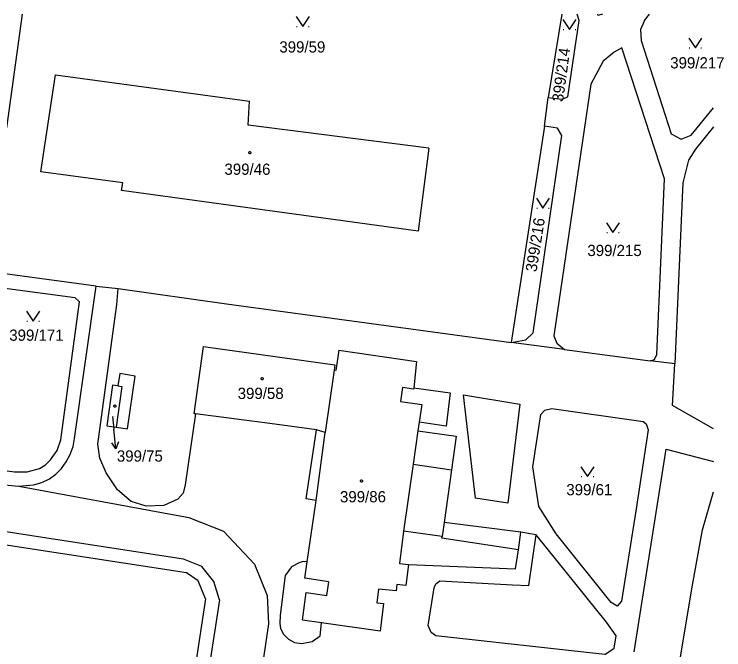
# Model space of a CAD drawing. Extents: x -851495 to -851222, y -1010479 to -1010202.
# Drawn here: x -851333.3 to -851225.9, y -1010299.4 to -1010203.3 of the extents above; entities that cross this region are included whole.
import ezdxf

# ---------------------------------------------------------------- set-up
doc = ezdxf.new("R2010")
doc.units = 0
for name, color, linetype in [('1', 7, 'Continuous'), ('12', 7, 'Continuous'), ('2', 7, 'Continuous'), ('3', 7, 'Continuous'), ('4', 7, 'Continuous'), ('5', 7, 'Continuous'), ('7', 7, 'Continuous')]:
    doc.layers.add(name, color=color, linetype=linetype)

# ---------------------------------------------------------------- blocks, each defined once
blk = doc.blocks.new('314')
for p, q in [((-0.95, 0), (-0.85, 0)), ((0.85, 0), (0.95, 0))]:
    blk.add_line(p, q)
blk.add_lwpolyline([(-1, 1.5), (0, 0), (1, 1.5)])
blk = doc.blocks.new('10292')
blk.add_line((0, 3), (0, 0))
blk.add_lwpolyline([(-0.5, 2), (0, 3), (0.5, 2)])
blk = doc.blocks.new('404')
blk.add_lwpolyline([(0, 0.17), (0.1, 0.15), (0.15, 0.06), (0.17, 0), (0.15, -0.09), (0.07, -0.16), (0, -0.17), (-0.09, -0.14), (-0.15, -0.08), (-0.17, 0), (-0.15, 0.09), (-0.07, 0.16), (0, 0.17)])

msp = doc.modelspace()

# ---------------------------------------------------------------- linework, layer by layer
at = {"layer": '1'}
for p, q in [((-851332.03, -1010203.26), (-851334.4, -1010220.43)), ((-851250.46, -1010203.26), (-851252.5, -1010215.86)), ((-851247.84, -1010204.19), (-851248.14, -1010203.26)), ((-851244.95, -1010203.46), (-851245.01, -1010203.26)), ((-851244.27, -1010203.26), (-851244.95, -1010203.46)), ((-851237.92, -1010204.22), (-851237.16, -1010203.26)), ((-851249.53, -1010215.73), (-851247.84, -1010204.19)), ((-851237.92, -1010204.22), (-851238.56, -1010205.58)), ((-851238.56, -1010205.58), (-851238.43, -1010207.26)), ((-851238.43, -1010207.26), (-851233.9, -1010221.36)), ((-851241.37, -1010208.36), (-851242.53, -1010208.98)), ((-851234.92, -1010228.17), (-851241.37, -1010208.36)), ((-851242.53, -1010208.98), (-851244.17, -1010210.38)), ((-851244.17, -1010210.38), (-851246.06, -1010213.84)), ((-851329.23, -1010227.1), (-851326.99, -1010212.43)), ((-851326.99, -1010212.43), (-851297.68, -1010216.41)), ((-851246.06, -1010213.84), (-851251.65, -1010251.91)), ((-851253.05, -1010220.18), (-851252.5, -1010215.86)), ((-851252.5, -1010215.86), (-851250.44, -1010216.12)), ((-851250.44, -1010216.12), (-851249.53, -1010215.73)), ((-851297.88, -1010220.05), (-851297.68, -1010216.41)), ((-851230.87, -1010221.56), (-851227.5, -1010217.44)), ((-851270.53, -1010223.5), (-851297.88, -1010220.05)), ((-851253.05, -1010220.18), (-851258.09, -1010252.91)), ((-851251.08, -1010220.48), (-851253.05, -1010220.18)), ((-851250.42, -1010221.62), (-851251.08, -1010220.48)), ((-851227.5, -1010220.29), (-851230.21, -1010223.65)), ((-851233.9, -1010221.36), (-851232.4, -1010222.15)), ((-851232.4, -1010222.15), (-851230.87, -1010221.56)), ((-851254.8, -1010251.46), (-851250.42, -1010221.62)), ((-851270.53, -1010223.5), (-851272.17, -1010236.09)), ((-851230.21, -1010223.65), (-851231.29, -1010225.34)), ((-851231.29, -1010225.34), (-851232.13, -1010228.78)), ((-851316.84, -1010228.77), (-851329.23, -1010227.1)), ((-851317.04, -1010229.92), (-851316.84, -1010228.77)), ((-851236.07, -1010254.72), (-851234.92, -1010228.17)), ((-851232.13, -1010228.78), (-851233.33, -1010256.15)), ((-851272.17, -1010236.09), (-851317.04, -1010229.92)), ((-851324.05, -1010246.13), (-851347.89, -1010243.01)), ((-851320.86, -1010244.4), (-851337.25, -1010242.19)), ((-851324.12, -1010267.41), (-851320.86, -1010244.4)), ((-851320.86, -1010244.4), (-851317.53, -1010244.75)), ((-851317.53, -1010244.75), (-851301.15, -1010247.03)), ((-851323.38, -1010246.75), (-851324.05, -1010246.13)), ((-851326.2, -1010267.63), (-851323.38, -1010246.75)), ((-851301.15, -1010247.03), (-851272.18, -1010251.01)), ((-851272.18, -1010251.01), (-851258.09, -1010252.91)), ((-851255.88, -1010252.52), (-851254.8, -1010251.46)), ((-851258.09, -1010252.91), (-851255.88, -1010252.52)), ((-851251.65, -1010251.91), (-851251.18, -1010253)), ((-851306.04, -1010263.67), (-851304.62, -1010253.53)), ((-851304.62, -1010253.53), (-851284.78, -1010256.27)), ((-851250.03, -1010253.97), (-851258.09, -1010252.91)), ((-851251.18, -1010253), (-851250.03, -1010253.97)), ((-851284.14, -1010254.06), (-851284.64, -1010257.12)), ((-851284.14, -1010254.06), (-851272.4, -1010255.76)), ((-851250.03, -1010253.97), (-851237.09, -1010255.66)), ((-851236.43, -1010255.45), (-851236.07, -1010254.72)), ((-851272.4, -1010255.76), (-851272.83, -1010259.74)), ((-851237.09, -1010255.66), (-851236.43, -1010255.45)), ((-851233.33, -1010256.15), (-851237.09, -1010255.66)), ((-851284.78, -1010256.27), (-851284.89, -1010257.08)), ((-851233.71, -1010262.45), (-851233.33, -1010256.15)), ((-851317.28, -1010257.61), (-851317.57, -1010259.46)), ((-851314.97, -1010257.98), (-851317.28, -1010257.61)), ((-851316.12, -1010265.93), (-851314.97, -1010257.98)), ((-851284.89, -1010257.08), (-851286.23, -1010266.49)), ((-851284.64, -1010257.12), (-851284.89, -1010257.08)), ((-851318.39, -1010259.34), (-851319.26, -1010265.51)), ((-851317.57, -1010259.46), (-851318.39, -1010259.34)), ((-851272.83, -1010259.74), (-851267.31, -1010260.51)), ((-851267.31, -1010260.51), (-851267.94, -1010265.54)), ((-851227.5, -1010265.95), (-851233.71, -1010262.45)), ((-851305.83, -1010263.7), (-851306.04, -1010263.67)), ((-851294.6, -1010265.16), (-851305.83, -1010263.7)), ((-851319.26, -1010265.51), (-851317.85, -1010265.7)), ((-851287.55, -1010266.1), (-851294.6, -1010265.16)), ((-851272.01, -1010264.96), (-851272.2, -1010266.24)), ((-851267.94, -1010265.54), (-851272.01, -1010264.96)), ((-851317.85, -1010265.7), (-851316.12, -1010265.93)), ((-851289.09, -1010276.53), (-851287.55, -1010266.1)), ((-851286.23, -1010266.49), (-851287.55, -1010266.1)), ((-851272.2, -1010266.24), (-851266.43, -1010267.07)), ((-851326.78, -1010269.25), (-851326.2, -1010267.63)), ((-851324.36, -1010268.65), (-851324.12, -1010267.41)), ((-851266.43, -1010267.07), (-851267.12, -1010272.13)), ((-851324.79, -1010269.84), (-851324.36, -1010268.65)), ((-851327.78, -1010270.65), (-851326.78, -1010269.25)), ((-851325.38, -1010270.93), (-851324.79, -1010269.84)), ((-851328.52, -1010271.39), (-851327.78, -1010270.65)), ((-851326.12, -1010271.93), (-851325.38, -1010270.93)), ((-851342.87, -1010271.15), (-851333.23, -1010272.48)), ((-851331.29, -1010272.46), (-851329.42, -1010271.93)), ((-851329.42, -1010271.93), (-851328.52, -1010271.39)), ((-851326.97, -1010272.79), (-851326.12, -1010271.93)), ((-851333.23, -1010272.48), (-851331.29, -1010272.46)), ((-851327.94, -1010273.51), (-851326.97, -1010272.79)), ((-851267.12, -1010272.13), (-851268.25, -1010280.14)), ((-851330.32, -1010274.43), (-851329.08, -1010274.09)), ((-851329.08, -1010274.09), (-851327.94, -1010273.51)), ((-851334.74, -1010274.41), (-851332.53, -1010274.61)), ((-851332.53, -1010274.61), (-851330.32, -1010274.43)), ((-851332.53, -1010274.61), (-851306.84, -1010279.38)), ((-851229.17, -1010281.24), (-851227.5, -1010275.5)), ((-851307.21, -1010287.72), (-851381.22, -1010276.44)), ((-851287.6, -1010276.78), (-851289.09, -1010276.53)), ((-851288.93, -1010286.05), (-851287.6, -1010276.78)), ((-851306.84, -1010279.38), (-851301.62, -1010281.43)), ((-851268.25, -1010280.14), (-851268.55, -1010282.25)), ((-851301.62, -1010281.43), (-851296.91, -1010286.42)), ((-851274.37, -1010281.41), (-851275, -1010286.31)), ((-851268.55, -1010282.25), (-851274.37, -1010281.41)), ((-851230.79, -1010290.13), (-851229.17, -1010281.24)), ((-851296.91, -1010286.42), (-851294.98, -1010291.17)), ((-851289.29, -1010288.55), (-851288.93, -1010286.05)), ((-851275, -1010286.31), (-851273.63, -1010286.48)), ((-851273.63, -1010286.48), (-851274.02, -1010289.65)), ((-851305.45, -1010288.92), (-851307.21, -1010287.72)), ((-851304.33, -1010291.66), (-851305.45, -1010288.92)), ((-851285.67, -1010289.07), (-851289.29, -1010288.55)), ((-851285.99, -1010291.16), (-851285.67, -1010289.07)), ((-851278.15, -1010290.18), (-851278.4, -1010292.25)), ((-851275.5, -1010290.47), (-851278.15, -1010290.18)), ((-851275.41, -1010289.51), (-851275.5, -1010290.47)), ((-851274.02, -1010289.65), (-851275.41, -1010289.51)), ((-851232.63, -1010301.37), (-851230.79, -1010290.13)), ((-851294.98, -1010291.17), (-851294.79, -1010295.43)), ((-851289.64, -1010294.89), (-851289.11, -1010290.69)), ((-851289.11, -1010290.69), (-851285.99, -1010291.16)), ((-851304.33, -1010291.66), (-851312.49, -1010345.66)), ((-851278.4, -1010292.25), (-851277.41, -1010292.37)), ((-851277.41, -1010292.37), (-851277.91, -1010296.55)), ((-851294.79, -1010295.43), (-851296.61, -1010307.61)), ((-851286.76, -1010295.3), (-851289.64, -1010294.89)), ((-851277.91, -1010296.55), (-851286.76, -1010295.3))]:
    msp.add_line(p, q, dxfattribs=at)
at = {"layer": '12'}
for p, q in [((-851329.23, -1010227.1), (-851326.99, -1010212.43)), ((-851326.99, -1010212.43), (-851297.68, -1010216.41)), ((-851297.88, -1010220.05), (-851297.68, -1010216.41)), ((-851270.53, -1010223.5), (-851297.88, -1010220.05)), ((-851270.53, -1010223.5), (-851272.17, -1010236.09)), ((-851316.84, -1010228.77), (-851329.23, -1010227.1)), ((-851317.04, -1010229.92), (-851316.84, -1010228.77)), ((-851272.17, -1010236.09), (-851317.04, -1010229.92)), ((-851306.04, -1010263.67), (-851304.62, -1010253.53)), ((-851304.62, -1010253.53), (-851284.78, -1010256.27)), ((-851284.14, -1010254.06), (-851284.64, -1010257.12)), ((-851284.14, -1010254.06), (-851272.4, -1010255.76)), ((-851272.4, -1010255.76), (-851272.83, -1010259.74)), ((-851284.78, -1010256.27), (-851284.89, -1010257.08)), ((-851284.89, -1010257.08), (-851286.23, -1010266.49)), ((-851284.89, -1010257.08), (-851286.23, -1010266.49)), ((-851284.64, -1010257.12), (-851284.89, -1010257.08)), ((-851318.39, -1010259.34), (-851319.26, -1010265.51)), ((-851317.57, -1010259.46), (-851318.39, -1010259.34)), ((-851316.97, -1010259.54), (-851317.85, -1010265.7)), ((-851317.57, -1010259.46), (-851316.97, -1010259.54)), ((-851274.53, -1010259.7), (-851274.84, -1010261.83)), ((-851272.85, -1010259.94), (-851274.53, -1010259.7)), ((-851272.83, -1010259.74), (-851272.85, -1010259.94)), ((-851274.84, -1010261.83), (-851271.63, -1010262.29)), ((-851271.63, -1010262.29), (-851272.01, -1010264.96)), ((-851305.83, -1010263.7), (-851306.04, -1010263.67)), ((-851294.6, -1010265.16), (-851305.83, -1010263.7)), ((-851319.26, -1010265.51), (-851317.85, -1010265.7)), ((-851287.55, -1010266.1), (-851294.6, -1010265.16)), ((-851272.01, -1010264.96), (-851272.2, -1010266.24)), ((-851287.6, -1010276.78), (-851286.23, -1010266.49)), ((-851286.23, -1010266.49), (-851287.55, -1010266.1)), ((-851272.2, -1010266.24), (-851272.92, -1010271.3)), ((-851272.92, -1010271.3), (-851274.37, -1010281.41)), ((-851288.93, -1010286.05), (-851287.6, -1010276.78)), ((-851274.37, -1010281.41), (-851275, -1010286.31)), ((-851289.29, -1010288.55), (-851288.93, -1010286.05)), ((-851275, -1010286.31), (-851273.63, -1010286.48)), ((-851273.63, -1010286.48), (-851274.02, -1010289.65)), ((-851285.67, -1010289.07), (-851289.29, -1010288.55)), ((-851285.99, -1010291.16), (-851285.67, -1010289.07)), ((-851278.15, -1010290.18), (-851278.4, -1010292.25)), ((-851275.5, -1010290.47), (-851278.15, -1010290.18)), ((-851275.41, -1010289.51), (-851275.5, -1010290.47)), ((-851274.02, -1010289.65), (-851275.41, -1010289.51)), ((-851289.64, -1010294.89), (-851289.11, -1010290.69)), ((-851289.11, -1010290.69), (-851285.99, -1010291.16)), ((-851278.4, -1010292.25), (-851277.41, -1010292.37)), ((-851277.41, -1010292.37), (-851277.91, -1010296.55)), ((-851286.76, -1010295.3), (-851289.64, -1010294.89)), ((-851277.91, -1010296.55), (-851286.76, -1010295.3))]:
    msp.add_line(p, q, dxfattribs=at)
at = {"layer": '4'}
for p, q in [((-851317.73, -1010247.16), (-851317.53, -1010244.75)), ((-851320.63, -1010268.25), (-851317.73, -1010247.16)), ((-851316.97, -1010259.54), (-851317.85, -1010265.7)), ((-851317.57, -1010259.46), (-851316.97, -1010259.54)), ((-851274.53, -1010259.7), (-851274.84, -1010261.83)), ((-851272.85, -1010259.94), (-851274.53, -1010259.7)), ((-851272.83, -1010259.74), (-851272.85, -1010259.94)), ((-851263.48, -1010276.46), (-851265.33, -1010260.82)), ((-851265.33, -1010260.82), (-851256.8, -1010262.24)), ((-851274.84, -1010261.83), (-851271.63, -1010262.29)), ((-851271.63, -1010262.29), (-851272.01, -1010264.96)), ((-851256.8, -1010262.24), (-851258.6, -1010277.17)), ((-851253.61, -1010263.8), (-851253.02, -1010263.15)), ((-851253.02, -1010263.15), (-851251.96, -1010262.86)), ((-851251.96, -1010262.86), (-851238.12, -1010264.83)), ((-851305.83, -1010263.7), (-851307.42, -1010274.44)), ((-851254.82, -1010271.69), (-851253.61, -1010263.8)), ((-851238.12, -1010264.83), (-851237.67, -1010265.22)), ((-851237.67, -1010265.22), (-851237.4, -1010266.11)), ((-851287.6, -1010276.78), (-851286.23, -1010266.49)), ((-851272.2, -1010266.24), (-851272.92, -1010271.3)), ((-851237.4, -1010266.11), (-851239.21, -1010278.05)), ((-851320.3, -1010270.38), (-851320.63, -1010268.25)), ((-851239.52, -1010299.69), (-851234.68, -1010269.05)), ((-851234.68, -1010269.05), (-851227.5, -1010270.87)), ((-851319.36, -1010272.63), (-851320.3, -1010270.38)), ((-851272.92, -1010271.3), (-851274.37, -1010281.41)), ((-851272.92, -1010271.3), (-851267.12, -1010272.13)), ((-851253.94, -1010277.71), (-851254.82, -1010271.69)), ((-851317.65, -1010275.19), (-851319.36, -1010272.63)), ((-851327.64, -1010282.59), (-851380.68, -1010274.4)), ((-851315.58, -1010276.96), (-851317.65, -1010275.19)), ((-851307.42, -1010274.44), (-851307.72, -1010275.69)), ((-851307.72, -1010275.69), (-851308.52, -1010276.58)), ((-851313.29, -1010277.63), (-851315.58, -1010276.96)), ((-851308.52, -1010276.58), (-851310.64, -1010277.56)), ((-851258.6, -1010277.17), (-851263.48, -1010276.46)), ((-851310.64, -1010277.56), (-851313.29, -1010277.63)), ((-851251.32, -1010281.81), (-851253.94, -1010277.71)), ((-851239.21, -1010278.05), (-851241.44, -1010292)), ((-851256.65, -1010281.59), (-851268.25, -1010280.14)), ((-851256.98, -1010284.25), (-851256.65, -1010281.59)), ((-851254.32, -1010282), (-851256.65, -1010281.59)), ((-851307.63, -1010285.64), (-851327.64, -1010282.59)), ((-851268.58, -1010282.48), (-851268.55, -1010282.25)), ((-851256.98, -1010284.25), (-851268.58, -1010282.48)), ((-851255.41, -1010289.64), (-851254.32, -1010282)), ((-851243.67, -1010295.19), (-851254.32, -1010282)), ((-851243, -1010292.19), (-851251.32, -1010281.81)), ((-851257.47, -1010287.1), (-851256.98, -1010284.25)), ((-851304.9, -1010286.78), (-851307.63, -1010285.64)), ((-851303.05, -1010289.06), (-851304.9, -1010286.78)), ((-851291.31, -1010286.82), (-851292.26, -1010288.15)), ((-851290.04, -1010286.14), (-851291.31, -1010286.82)), ((-851289.51, -1010286.02), (-851290.04, -1010286.14)), ((-851288.93, -1010286.05), (-851289.51, -1010286.02)), ((-851273.63, -1010286.48), (-851257.47, -1010287.1)), ((-851302.19, -1010291.81), (-851303.05, -1010289.06)), ((-851292.26, -1010288.15), (-851293.05, -1010294.14)), ((-851269.48, -1010289.41), (-851268.89, -1010288.96)), ((-851268.89, -1010288.96), (-851257.92, -1010289.52)), ((-851270.63, -1010295.71), (-851269.76, -1010289.97)), ((-851269.76, -1010289.97), (-851269.48, -1010289.41)), ((-851257.92, -1010289.52), (-851255.41, -1010289.64)), ((-851302.19, -1010291.81), (-851310.67, -1010345.99)), ((-851242.06, -1010292.77), (-851243, -1010292.19)), ((-851241.44, -1010292), (-851242.06, -1010292.77)), ((-851293.05, -1010294.14), (-851293.1, -1010295.4)), ((-851293.1, -1010295.4), (-851292.96, -1010296.15)), ((-851287.01, -1010297.27), (-851286.76, -1010295.3)), ((-851242.23, -1010297.27), (-851243.67, -1010295.19)), ((-851292.96, -1010296.15), (-851292.51, -1010297.01)), ((-851270.2, -1010296.74), (-851270.63, -1010295.71)), ((-851292.51, -1010297.01), (-851291.76, -1010297.76)), ((-851291.76, -1010297.76), (-851290.86, -1010298.25)), ((-851288.2, -1010298.1), (-851287.01, -1010297.27)), ((-851269.5, -1010297.24), (-851270.2, -1010296.74)), ((-851243.92, -1010300.08), (-851269.5, -1010297.24)), ((-851242.55, -1010299.1), (-851242.23, -1010297.27)), ((-851290.86, -1010298.25), (-851289.74, -1010298.42)), ((-851289.74, -1010298.42), (-851288.2, -1010298.1)), ((-851243.92, -1010300.08), (-851242.55, -1010299.1))]:
    msp.add_line(p, q, dxfattribs=at)
at = {"layer": '7'}
msp.add_line((-851318.4, -1010264.09), (-851318.19, -1010266.01), dxfattribs=at)

# ---------------------------------------------------------------- block references
at = {"layer": '3'}
for p in [(-851289.62, -1010205.13), (-851249.28, -1010205.55), (-851230.25, -1010208.36), (-851253.29, -1010232.59), (-851242.71, -1010236.29), (-851330.4, -1010249.67), (-851246.55, -1010273.18)]:
    msp.add_blockref('314', p, dxfattribs=at)
at = {"layer": '5'}
for p in [(-851297.62, -1010224.2), (-851295.76, -1010258.37), (-851318.04, -1010262.52), (-851280.73, -1010273.85)]:
    msp.add_blockref('404', p, dxfattribs=at)
at = {"layer": '7', "rotation": -173.73142099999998}
msp.add_blockref('10292', (-851318.19, -1010266.01), dxfattribs=at)

# ---------------------------------------------------------------- texts
at = {"layer": '2'}
for s, height, p in [('399/59', 1.7, (-851293.16, -1010209.06)), ('399/217', 1.7, (-851234.05, -1010211.46)), ('399/46', 1.7, (-851301.46, -1010227.55)), ('399/215', 1.7, (-851246.58, -1010239.83)), ('399/171', 1.7, (-851334, -1010252.64)), ('399/58', 1.7, (-851299.46, -1010261.44)), ('399/75', 0.1, (-851318.39, -1010264.09)), ('399/61', 1.7, (-851249.76, -1010276)), ('399/86', 1.7, (-851283.99, -1010277.07))]:
    msp.add_text(s, height=height, dxfattribs=at).set_placement(p)
for s, rotation, p in [('399/214', 82.277, (-851250.26, -1010216.61)), ('399/216', 81.016, (-851254.27, -1010242.31))]:
    msp.add_text(s, height=1.7, rotation=rotation, dxfattribs=at).set_placement(p)
at = {"layer": '7'}
msp.add_text('399/75', height=1.7, dxfattribs=at).set_placement((-851317.73, -1010270.91))

doc.saveas('drawing.dxf')
